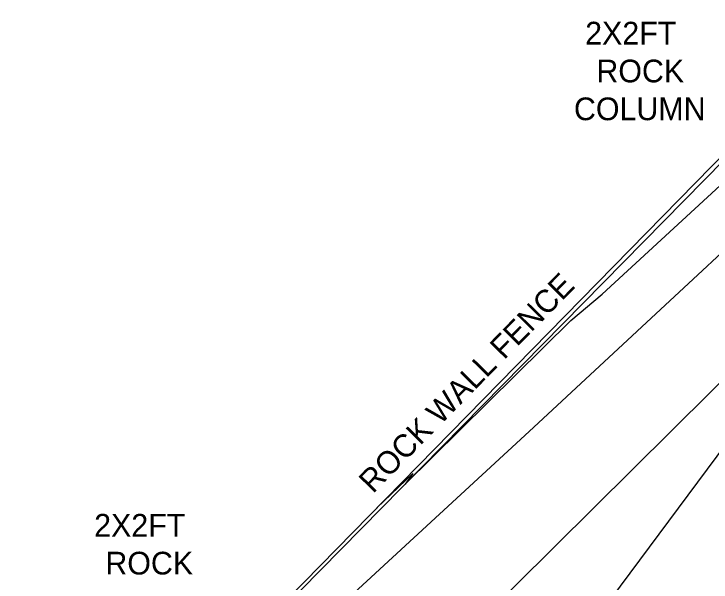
# Model space of a CAD drawing. Extents: x 2250985 to 2256614, y 13788366 to 13792478.
# Drawn here: x 2255462.39 to 2255499.23, y 13791414.59 to 13791444.61 of the extents above; entities that cross this region are included whole.
import ezdxf

# ---------------------------------------------------------------- set-up
doc = ezdxf.new("R2010")
doc.units = 0
for name, color, linetype in [('E_ROW_Driveway', 7, 'Continuous'), ('E_ROW_Driveway_3D', 7, 'Continuous'), ('E_ROW_Driveway_3D_R', 7, 'Continuous'), ('E_Struc_PavedArea', 7, 'Continuous'), ('E_Terrain_Island', 7, 'Continuous'), ('E_Terrain_Triangle_Vertices', 7, 'Continuous'), ('E_Util_SanManhole', 7, 'Continuous')]:
    doc.layers.add(name, color=color, linetype=linetype)

msp = doc.modelspace()

# ---------------------------------------------------------------- linework, layer by layer
at = {"layer": 'E_ROW_Driveway'}
msp.add_lwpolyline([(2255682.15, 13791623.74), (2255655.06, 13791595.94), (2255584.95, 13791524), (2255514.86, 13791452.11), (2255467.95, 13791404.4), (2255467.91, 13791404.83)], dxfattribs=at)
at = {"layer": 'E_ROW_Driveway_3D'}
msp.add_spline([(2255757.41, 13791636.85), (2255687.94, 13791564.76), (2255617.79, 13791493.04), (2255547.24, 13791420.85), (2255520.67, 13791393.29), (2255497.6, 13791368.95), (2255478.26, 13791349.63), (2255448.39, 13791320.87), (2255406.6, 13791278.93), (2255336.25, 13791208.32), (2255265.61, 13791136.29), (2255195.22, 13791064.79), (2255147.92, 13791015.98)], degree=3, dxfattribs=at)
at = {"layer": 'E_ROW_Driveway_3D_R'}
msp.add_lwpolyline([(2255733.63, 13791659.53), (2255663.87, 13791587.33), (2255592.28, 13791516.92), (2255480.61, 13791406.21)], dxfattribs=at)
at = {"layer": 'E_Struc_PavedArea'}
msp.add_line((2255502.73, 13791440.11), (2255472.75, 13791409.51), dxfattribs=at)
at = {"layer": 'E_Util_SanManhole'}
for points in [[(2255481.568, 13791418.51), (2255483.467, 13791420.332), (2255483.065, 13791419.773), (2255491.814, 13791428.413), (2255493.482, 13791429.809), (2255506.381, 13791441.701), (2255556.726, 13791488.451), (2255557.689, 13791487.799), (2255556.829, 13791481.774), (2255534.517, 13791453.783), (2255505.529, 13791414.791), (2255507.865, 13791416.35), (2255508.147, 13791416.533), (2255507.889, 13791409.815), (2255506.153, 13791397.573), (2255507.263, 13791398.103), (2255507.556, 13791398.178), (2255507.651, 13791398.104), (2255525.838, 13791410.436)], [(2255470.909, 13791396.004), (2255471.027, 13791396.125), (2255471.256, 13791395.688), (2255471.261, 13791395.684), (2255472.34, 13791395.394), (2255474.651, 13791394.986), (2255476.972, 13791395.246), (2255479.084, 13791396.14), (2255481.162, 13791396.891), (2255481.365, 13791396.878), (2255480.664, 13791398.822), (2255481.897, 13791400.042), (2255485.147, 13791401.874), (2255503.176, 13791426.124), (2255512.516, 13791437.841), (2255512.876, 13791440.364), (2255510.944, 13791441.671)], [(2255508.697, 13791440.268), (2255489.614, 13791422.548), (2255476.301, 13791410.275), (2255474.79, 13791408.698), (2255472.806, 13791406.68), (2255471.375, 13791406.438), (2255466.231, 13791401.417), (2255466.195, 13791401.395), (2255467.763, 13791399.507), (2255468.123, 13791399.257), (2255468.141, 13791399.244), (2255468.115, 13791399.203), (2255467.972, 13791399.064), (2255467.69, 13791399.135), (2255468.174, 13791398.635), (2255470.861, 13791396.049), (2255470.909, 13791396.004)]]:
    msp.add_lwpolyline(points, dxfattribs=at)

# ---------------------------------------------------------------- texts
at = {"layer": 'E_Terrain_Island'}
msp.add_text('ROCK WALL FENCE', height=1.2, rotation=45.5864, dxfattribs=at).set_placement((2255481.364, 13791419.231))
at = {"layer": 'E_Terrain_Triangle_Vertices'}
for s, p in [('2X2FT ', (2255492.577, 13791442.999)), ('ROCK ', (2255493.17, 13791440.999)), ('COLUMN', (2255491.985, 13791438.999)), ('2X2FT ', (2255466.631, 13791416.992)), ('ROCK ', (2255467.223, 13791414.992))]:
    msp.add_text(s, height=1.2, dxfattribs=at).set_placement(p)

doc.saveas('drawing.dxf')
